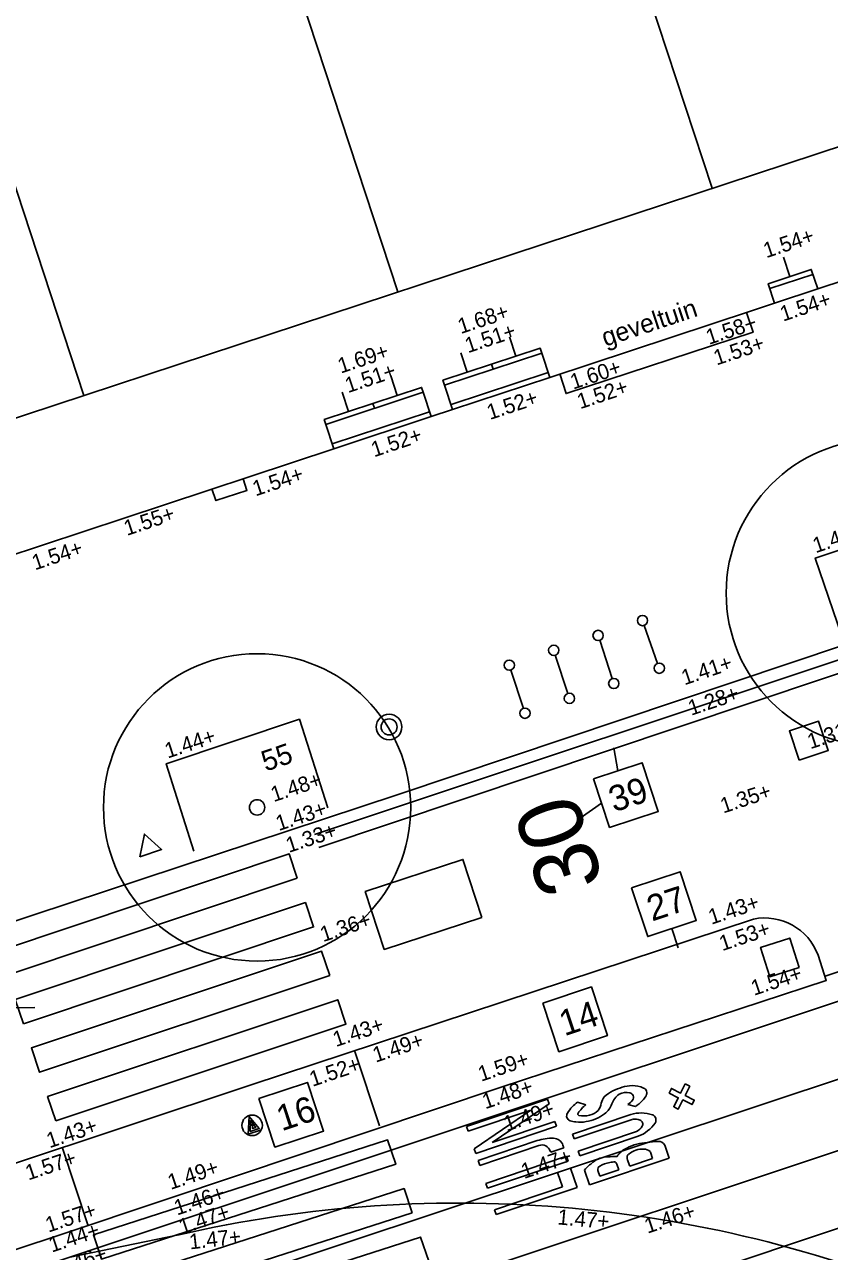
# Model space of a CAD drawing. Extents: x 122462 to 123306, y 485548 to 486417.
# Drawn here: x 122787.35 to 122803.07, y 486173.11 to 486197.06 of the extents above; entities that cross this region are included whole.
import ezdxf

# ---------------------------------------------------------------- set-up
doc = ezdxf.new("R2010")
doc.units = 0
for name, color, linetype in [('B meubilair trammast', 7, 'Continuous'), ('B nummers', 7, 'Continuous'), ('B-WE-AL-T25', 7, 'Continuous'), ('B-WE-AL-WERKGRENS-G', 7, 'Continuous'), ('B-WE-GR-BOOM-S', 7, 'Continuous'), ('B-WE-GR-BOOM_BOOMDIAMETER', 7, 'Continuous'), ('B-WE-OG-BEBOUWING_PORTIEK1-G', 7, 'Continuous'), ('B-WE-OG-BEBOUWING_TRAP-G', 7, 'Continuous'), ('B-WE-OG-HOOGTEPUNT-S', 7, 'Continuous'), ('B-WE-OG-TOPOGRAFIE_GEVELDETAIL-G', 7, 'Continuous'), ('B-WE-OG-TOPOKAART-G', 7, 'Continuous'), ('Level 4', 7, 'Continuous'), ('V markering 1-1 10 cm', 7, 'Continuous'), ('V markering figuratie', 7, 'Continuous'), ('V materiaalscheiding algemeen', 7, 'Continuous'), ('V meubilair fietsenrek', 7, 'Continuous'), ('V meubilair gele koker en bord', 7, 'Continuous'), ('V meubilair verkeersbord', 7, 'Continuous'), ('V meubilair vuilnisbak', 7, 'Continuous'), ('V opsluitband 100x200 mm', 7, 'Continuous'), ('V Rails', 7, 'Continuous'), ('V riool putdeksel', 7, 'Continuous'), ('V trottoirband 180-200x250 mm specie', 7, 'Continuous')]:
    doc.layers.add(name, color=color, linetype=linetype)

msp = doc.modelspace()

# ---------------------------------------------------------------- linework, layer by layer
at = {"layer": 'B meubilair trammast'}
msp.add_lwpolyline([(122789.595, 486180.815), (122790.022, 486180.956), (122789.686, 486181.256)], close=True, dxfattribs=at)
at = {"layer": 'B nummers'}
for p, q in [((122798.935, 486182.494), (122798.858, 486182.939)), ((122798.617, 486181.862), (122798.197, 486181.569)), ((122799.99, 486179.415), (122800.114, 486179.04)), ((122786.188, 486177.867), (122787.545, 486177.871)), ((122787.545, 486177.871), (122787.545, 486177.871))]:
    msp.add_line(p, q, dxfattribs=at)
for points in [[(122798.46, 486182.337), (122799.41, 486182.651), (122799.723, 486181.701), (122798.773, 486181.388)], [(122799.202, 486180.208), (122800.152, 486180.521), (122800.465, 486179.571), (122799.516, 486179.258)], [(122797.468, 486177.96), (122798.417, 486178.273), (122798.731, 486177.324), (122797.781, 486177.01)], [(122791.922, 486176.098), (122792.872, 486176.411), (122793.185, 486175.461), (122792.235, 486175.148)]]:
    msp.add_lwpolyline(points, close=True, dxfattribs=at)
at = {"layer": 'B-WE-AL-WERKGRENS-G'}
msp.add_lwpolyline([(122857.632, 486078.279), (122830.484, 486160.606), (122900.937, 486183.81), (122887.855, 486222.555), (122665.445, 486149.273), (122678.196, 486110.449), (122807.072, 486152.895), (122835.324, 486068.154)], dxfattribs=at)
at = {"layer": 'B-WE-GR-BOOM-S'}
for centre, radius in [((122804.049, 486185.96), 3), ((122791.888, 486181.778), 3), ((122791.888, 486181.778), 0.15)]:
    msp.add_circle(centre, radius, dxfattribs=at)
for start, end in [(0, 180), (180, 0)]:
    msp.add_arc((122791.888, 486181.778), 0.15, start, end, dxfattribs=at)
at = {"layer": 'B-WE-OG-BEBOUWING_PORTIEK1-G'}
for p, q in [((122796.943, 486190.583), (122796.817, 486190.963)), ((122795.993, 486190.27), (122795.868, 486190.65)), ((122796.499, 486190.332), (122796.468, 486190.427)), ((122794.625, 486189.819), (122794.5, 486190.198)), ((122793.675, 486189.505), (122793.55, 486189.885)), ((122794.181, 486189.567), (122794.15, 486189.662))]:
    msp.add_line(p, q, dxfattribs=at)
for points in [[(122795.55, 486190.018), (122797.449, 486190.645), (122797.418, 486190.74), (122795.518, 486190.113)], [(122793.232, 486189.254), (122795.131, 486189.88), (122795.1, 486189.975), (122793.2, 486189.348)]]:
    msp.add_lwpolyline(points, close=True, dxfattribs=at)
at = {"layer": 'B-WE-OG-BEBOUWING_TRAP-G'}
for points in [[(122797.574, 486190.265), (122795.675, 486189.638)], [(122797.606, 486190.17), (122795.706, 486189.543)], [(122795.256, 486189.5), (122793.357, 486188.874)], [(122795.288, 486189.405), (122793.389, 486188.779)]]:
    msp.add_lwpolyline(points, dxfattribs=at)
at = {"layer": 'B-WE-OG-TOPOGRAFIE_GEVELDETAIL-G'}
msp.add_line((122802.291, 486192.137), (122802.166, 486192.517), dxfattribs=at)
msp.add_lwpolyline([(122801.995, 486191.619), (122802.837, 486191.896), (122802.712, 486192.276), (122801.87, 486191.998)], close=True, dxfattribs=at)
msp.add_lwpolyline([(122802.743, 486192.181), (122801.901, 486191.904)], dxfattribs=at)
at = {"layer": 'B-WE-OG-TOPOKAART-G'}
for p, q in [((122797.606, 486190.17), (122797.449, 486190.645)), ((122793.389, 486188.779), (122793.232, 486189.254))]:
    msp.add_line(p, q, dxfattribs=at)
for points in [[(122802.837, 486191.896), (122806.557, 486193.124)], [(122797.606, 486190.17), (122801.563, 486191.476), (122801.995, 486191.619)], [(122795.131, 486189.88), (122795.288, 486189.405), (122795.706, 486189.543), (122795.55, 486190.018)], [(122785.346, 486186.125), (122789.289, 486187.426), (122793.389, 486188.779)]]:
    msp.add_lwpolyline(points, dxfattribs=at)
at = {"layer": 'Level 4'}
for p, q in [((122800.777, 486193.863), (122797.737, 486203.09)), ((122794.639, 486191.841), (122791.192, 486202.302)), ((122788.501, 486189.818), (122785.054, 486200.279))]:
    msp.add_line(p, q, dxfattribs=at)
at = {"layer": 'V markering 1-1 10 cm'}
for points in [[(122820.303, 486190.322), (122804.286, 486185), (122793.007, 486181.252)], [(122820.386, 486190.104), (122804.368, 486184.77), (122793.094, 486180.995)]]:
    msp.add_lwpolyline(points, dxfattribs=at)
at = {"layer": 'V markering figuratie'}
for p, q in [((122712.845, 486143.511), (122860.885, 486192.728)), ((122795.98, 486175.553), (122797.56, 486176.083)), ((122797.56, 486176.083), (122797.591, 486175.992)), ((122798.309, 486175.974), (122798.148, 486176.024)), ((122796.012, 486175.459), (122797.234, 486175.869)), ((122796.127, 486175.117), (122797.234, 486175.869)), ((122796.481, 486175.238), (122797.591, 486175.992)), ((122799.185, 486175.785), (122798.047, 486175.403)), ((122799.13, 486175.982), (122799.278, 486175.939)), ((122795.98, 486175.553), (122796.012, 486175.459)), ((122796.157, 486175.025), (122797.737, 486175.555)), ((122796.481, 486175.238), (122797.706, 486175.649)), ((122797.706, 486175.649), (122797.737, 486175.555)), ((122799.216, 486175.69), (122798.079, 486175.308)), ((122798.079, 486175.308), (122798.047, 486175.403)), ((122799.297, 486175.453), (122798.159, 486175.072)), ((122799.328, 486175.36), (122798.191, 486174.978)), ((122796.127, 486175.117), (122796.157, 486175.025)), ((122796.204, 486174.886), (122797.361, 486175.274)), ((122796.235, 486174.792), (122797.392, 486175.181)), ((122797.615, 486175.07), (122797.622, 486175.049)), ((122797.622, 486175.049), (122797.878, 486175.135)), ((122797.861, 486175.185), (122797.878, 486175.135)), ((122798.191, 486174.978), (122798.159, 486175.072)), ((122799.935, 486174.93), (122799.85, 486175.184)), ((122796.204, 486174.886), (122796.235, 486174.792)), ((122796.354, 486174.44), (122797.933, 486174.97)), ((122796.385, 486174.346), (122797.965, 486174.876)), ((122797.933, 486174.97), (122797.965, 486174.876)), ((122799.935, 486174.93), (122798.381, 486174.409)), ((122799.165, 486174.779), (122799.118, 486174.915)), ((122799.612, 486174.929), (122799.165, 486174.779)), ((122799.612, 486174.929), (122799.571, 486175.051)), ((122797.755, 486174.654), (122798.011, 486174.74)), ((122797.755, 486174.654), (122797.85, 486174.371)), ((122798.011, 486174.74), (122798.137, 486174.363)), ((122798.381, 486174.409), (122798.283, 486174.7)), ((122798.581, 486174.584), (122798.545, 486174.692)), ((122798.95, 486174.707), (122798.581, 486174.584)), ((122798.95, 486174.707), (122798.912, 486174.818)), ((122796.354, 486174.44), (122796.385, 486174.346)), ((122796.526, 486173.927), (122797.85, 486174.371)), ((122796.557, 486173.833), (122798.137, 486174.363)), ((122796.526, 486173.927), (122796.557, 486173.833))]:
    msp.add_line(p, q, dxfattribs=at)
for points in [[(122792.673, 486180.395), (122787.006, 486178.506), (122786.848, 486178.98), (122792.515, 486180.869)], [(122796.278, 486179.632), (122794.371, 486179.006), (122793.999, 486180.136), (122795.907, 486180.762)], [(122787.323, 486177.557), (122792.99, 486179.446), (122792.831, 486179.921), (122787.164, 486178.032)], [(122793.306, 486178.498), (122787.639, 486176.609), (122787.481, 486177.083), (122793.148, 486178.972)], [(122787.955, 486175.66), (122793.622, 486177.549), (122793.464, 486178.023), (122787.797, 486176.134)], [(122800.25, 486176.381), (122800.339, 486176.336), (122800.249, 486176.157), (122800.427, 486176.067), (122800.382, 486175.978), (122800.204, 486176.068), (122800.113, 486175.889), (122800.024, 486175.935), (122800.114, 486176.113), (122799.936, 486176.203), (122799.981, 486176.293), (122800.16, 486176.202)], [(122788.851, 486172.962), (122794.597, 486174.813), (122794.436, 486175.287), (122788.69, 486173.436)], [(122794.918, 486173.866), (122789.172, 486172.015), (122789.012, 486172.488), (122794.758, 486174.339)], [(122789.494, 486171.068), (122795.24, 486172.919), (122795.079, 486173.392), (122789.333, 486171.541)]]:
    msp.add_lwpolyline(points, close=True, dxfattribs=at)
for centre, radius, start, end in [((122799.281, 486175.378), 0.974, 105.7088, 117.2175), ((122799.254, 486175.503), 0.846, 92.7722, 106.2036), ((122799.202, 486175.754), 0.595, 66.9883, 88.9869), ((122799.4, 486176.206), 0.101, 327.408, 69.7223), ((122798.531, 486175.465), 0.678, 124.405, 135.9831), ((122798.92, 486175.926), 0.322, 141.1952, 166.0199), ((122799.122, 486175.66), 0.651, 116.0926, 134.076), ((122799.166, 486175.881), 0.365, 124.346, 162.4962), ((122799.103, 486175.91), 0.307, 78.1602, 117.6453), ((122798.94, 486176.29), 0.362, 301.5906, 321.358), ((122799.142, 486176.117), 0.0964, 326.7844, 76.021), ((122798.797, 486176.63), 0.842, 304.8132, 317.0391), ((122799.145, 486176.332), 0.384, 314.1678, 332.0337), ((122798.032, 486175.757), 0.0987, 145.9999, 251.0729), ((122798.634, 486175.396), 0.8, 137.6166, 148.6856), ((122798.184, 486175.793), 0.0305, 146.646, 250.3833), ((122798.718, 486175.449), 0.666, 127.8663, 147.1353), ((122798.32, 486176.093), 0.327, 279.9995, 314.4525), ((122798.248, 486176.343), 0.692, 291.7137, 308.2006), ((122798.262, 486176.06), 0.35, 325.1158, 350.7379), ((122798.429, 486176.131), 0.413, 306.6578, 340.1843), ((122799.386, 486175.117), 0.698, 71.5011, 106.7457), ((122798.174, 486176.218), 0.581, 252.6238, 263.9155), ((122798.196, 486176.207), 0.573, 261.5616, 282.0156), ((122798.259, 486176.291), 0.534, 260.8073, 282.7699), ((122798.145, 486176.613), 0.981, 280.0069, 291.4687), ((122799.272, 486175.464), 0.233, 65.6586, 103.52), ((122799.205, 486175.668), 0.233, 293.1652, 331.0266), ((122799.087, 486176.014), 0.698, 290.22, 325.4646), ((122799.34, 486175.599), 0.0816, 326.8261, 70.6026), ((122799.57, 486175.677), 0.109, 327.5338, 70.0318), ((122797.652, 486174.406), 0.916, 88.5105, 108.5511), ((122797.671, 486175.121), 0.201, 18.5511, 88.5091), ((122797.448, 486175.014), 0.176, 18.5511, 108.5511), ((122799.278, 486174.736), 0.428, 112.9608, 147.3345), ((122799.621, 486174.1), 1.15, 106.0457, 116.3281), ((122799.464, 486174.611), 0.51, 110.3608, 128.0203), ((122799.423, 486174.663), 0.448, 87.5416, 107.6526), ((122799.686, 486173.623), 1.628, 96.3398, 103.6073), ((122799.432, 486174.912), 0.199, 48.7305, 87.258), ((122799.79, 486172.971), 2.287, 91.8384, 97.1266), ((122799.546, 486175.042), 0.0256, 18.8162, 48.7305), ((122799.733, 486175.128), 0.13, 25.5905, 97.1302), ((122799.291, 486173.779), 1.366, 128.1207, 137.585), ((122798.756, 486174.468), 0.493, 92.3332, 128.686), ((122798.913, 486174.168), 0.695, 101.5077, 118.5904), ((122798.745, 486177.331), 2.37, 269.7882, 274.1743), ((122798.867, 486174.382), 0.476, 88.6116, 101.2363), ((122798.848, 486174.798), 0.0675, 17.2951, 63.1089), ((122799.198, 486174.944), 0.0849, 124.7198, 198.9477), ((122798.611, 486174.716), 0.0697, 115.6203, 199.8544)]:
    msp.add_arc(centre, radius, start, end, dxfattribs=at)
at = {"layer": 'V materiaalscheiding algemeen'}
for points in [[(122802.962, 486178.476), (122818.617, 486183.717)], [(122793.267, 486181.77), (122792.716, 486183.498), (122790.114, 486182.629), (122790.652, 486180.921)]]:
    msp.add_lwpolyline(points, dxfattribs=at)
at = {"layer": 'V meubilair fietsenrek'}
for p, q in [((122799.71, 486184.588), (122799.448, 486185.33)), ((122798.823, 486184.291), (122798.579, 486185.039)), ((122797.956, 486184.001), (122797.712, 486184.749)), ((122797.089, 486183.711), (122796.845, 486184.459))]:
    msp.add_line(p, q, dxfattribs=at)
for centre in [(122799.415, 486185.424), (122798.548, 486185.134), (122797.681, 486184.844), (122796.814, 486184.554), (122799.743, 486184.494), (122798.854, 486184.196), (122797.987, 486183.906), (122797.12, 486183.616)]:
    msp.add_circle(centre, 0.1, dxfattribs=at)
at = {"layer": 'V meubilair gele koker en bord'}
msp.add_lwpolyline([(122802.474, 486178.656), (122802.291, 486179.227), (122801.72, 486179.044), (122801.903, 486178.473)], close=True, dxfattribs=at)
at = {"layer": 'V meubilair verkeersbord'}
msp.add_lwpolyline([(122791.953, 486175.482), (122791.714, 486175.402), (122791.732, 486175.748), (122791.931, 486175.514), (122791.755, 486175.456), (122791.759, 486175.668), (122791.863, 486175.534), (122791.798, 486175.512), (122791.797, 486175.554), (122791.782, 486175.602)], dxfattribs=at)
msp.add_circle((122791.791, 486175.573), 0.2, dxfattribs=at)
at = {"layer": 'V meubilair vuilnisbak'}
for radius in [0.25, 0.156]:
    msp.add_circle((122794.466, 486183.348), radius, dxfattribs=at)
at = {"layer": 'V opsluitband 100x200 mm'}
for points in [[(122801.449, 486191.437), (122801.575, 486191.052), (122797.922, 486189.855), (122797.798, 486190.238)], [(122791.615, 486188.192), (122791.69, 486187.964), (122791.083, 486187.765), (122791.007, 486187.995)], [(122803.306, 486185.122), (122802.789, 486186.643), (122804.788, 486187.304), (122805.271, 486185.801)]]:
    msp.add_lwpolyline(points, dxfattribs=at)
at = {"layer": 'V Rails'}
for p, q in [((122714.919, 486148.627), (122859.557, 486196.72)), ((122715.373, 486147.26), (122860.011, 486195.354)), ((122712.39, 486144.878), (122860.43, 486194.095)), ((122790.351, 486173.434), (122788.203, 486172.994))]:
    msp.add_line(p, q, dxfattribs=at)
msp.add_arc((122795.822, 486149.654), 24.402, 66.5251, 103.0007, dxfattribs=at)
at = {"layer": 'V riool putdeksel'}
msp.add_lwpolyline([(122802.473, 486182.702), (122803.043, 486182.89), (122802.855, 486183.46), (122802.285, 486183.272)], close=True, dxfattribs=at)
at = {"layer": 'V trottoirband 180-200x250 mm specie'}
for points in [[(122833.081, 486194.781), (122818.107, 486189.829), (122805.552, 486185.683), (122794.641, 486182.031), (122786.085, 486179.205)], [(122764.995, 486167.464), (122774.458, 486170.57), (122782.134, 486173.165), (122791.772, 486176.363), (122801.583, 486179.598)], [(122802.843, 486178.897), (122803.005, 486178.403), (122796.653, 486176.321), (122790.145, 486174.137), (122787.981, 486173.414), (122783.643, 486171.985), (122782.562, 486171.633), (122774.188, 486168.85), (122765.631, 486166.001), (122757.287, 486163.217), (122748.482, 486160.287), (122740.076, 486157.459), (122731.818, 486154.747)], [(122794.278, 486175.565), (122793.798, 486177.017)], [(122788.088, 486175.127), (122788.579, 486173.63)]]:
    msp.add_lwpolyline(points, dxfattribs=at)
msp.add_arc((122801.804, 486178.512), 1.108, 20.3372, 101.4841, dxfattribs=at)

# ---------------------------------------------------------------- texts
at = {"layer": 'B nummers'}
for s, p in [('39', (122798.858, 486181.679)), ('27', (122799.601, 486179.55)), ('14', (122797.89, 486177.31)), ('16', (122792.368, 486175.455))]:
    msp.add_text(s, height=0.5, rotation=18.2603, dxfattribs=at).set_placement(p)
at = {"layer": 'B-WE-AL-T25'}
msp.add_text('geveltuin', height=0.36, rotation=18.3134, dxfattribs=at).set_placement((122798.688, 486190.767))
at = {"layer": 'B-WE-GR-BOOM_BOOMDIAMETER'}
msp.add_text('55', height=0.4, rotation=18.7219, dxfattribs=at).set_placement((122792.054, 486182.474))
at = {"layer": 'B-WE-OG-HOOGTEPUNT-S'}
for s, rotation, p in [('1.54+', 18.2611, (122801.833, 486192.496)), ('1.54+', 18.2611, (122802.16, 486191.257)), ('1.68+', 18.2611, (122795.866, 486191.015)), ('1.51+', 18.2611, (122796.005, 486190.641)), ('1.58+', 18.2611, (122800.712, 486190.804)), ('1.53+', 18.2611, (122800.861, 486190.401)), ('1.69+', 18.2611, (122793.522, 486190.243)), ('1.51+', 18.2611, (122793.663, 486189.862)), ('1.60+', 18.2611, (122798.062, 486189.931)), ('1.52+', 18.2611, (122798.197, 486189.548)), ('1.52+', 18.2611, (122796.434, 486189.338)), ('1.52+', 18.2611, (122794.173, 486188.61)), ('1.54+', 18.2611, (122791.858, 486187.847)), ('1.55+', 18.2611, (122789.344, 486187.076)), ('1.46+', 18.2498, (122802.797, 486186.738)), ('1.54+', 18.2611, (122787.549, 486186.404)), ('1.41+', 18.5058, (122800.234, 486184.159)), ('1.28+', 18.5058, (122800.365, 486183.565)), ('1.44+', 18.2498, (122790.142, 486182.731)), ('1.31+', 18.2498, (122802.694, 486182.912)), ('1.48+', 18.2498, (122792.213, 486181.88)), ('1.35+', 18.2498, (122800.993, 486181.658)), ('1.43+', 18.2498, (122792.311, 486181.315)), ('1.33+', 18.2498, (122792.508, 486180.888)), ('1.43+', 18.3717, (122800.76, 486179.487)), ('1.36+', 18.2498, (122793.178, 486179.148)), ('1.53+', 18.3717, (122800.973, 486178.971)), ('1.54+', 18.3717, (122801.593, 486178.1)), ('1.43+', 18.405, (122793.426, 486177.099)), ('1.49+', 18.405, (122794.204, 486176.795)), ('1.52+', 18.405, (122792.97, 486176.324)), ('1.59+', 18.5511, (122796.263, 486176.422)), ('1.48+', 18.5511, (122796.345, 486175.886)), ('1.49+', 18.5511, (122796.76, 486175.45)), ('1.43+', 18.3786, (122787.833, 486175.124)), ('1.57+', 18.3786, (122787.421, 486174.496)), ('1.49+', 18.3786, (122790.201, 486174.313)), ('1.47+', 18.5511, (122797.102, 486174.525)), ('1.46+', 18.3786, (122790.324, 486173.812)), ('1.57+', 18.3786, (122787.813, 486173.478)), ('1.47+', 18.3786, (122790.417, 486173.441)), ('1.47+', 354.697, (122797.744, 486173.641)), ('1.46+', 18.3717, (122799.512, 486173.456)), ('1.44+', 18.3786, (122787.878, 486173.088)), ('1.47+', 6.4053, (122790.578, 486173.151)), ('1.46+', 18.3414, (122788.02, 486172.629))]:
    msp.add_text(s, height=0.3, rotation=rotation, dxfattribs=at).set_placement(p)
at = {"layer": 'V markering figuratie'}
msp.add_text('30', height=1.26, rotation=108.2384, dxfattribs=at).set_placement((122798.665, 486180.326))

doc.saveas('drawing.dxf')
